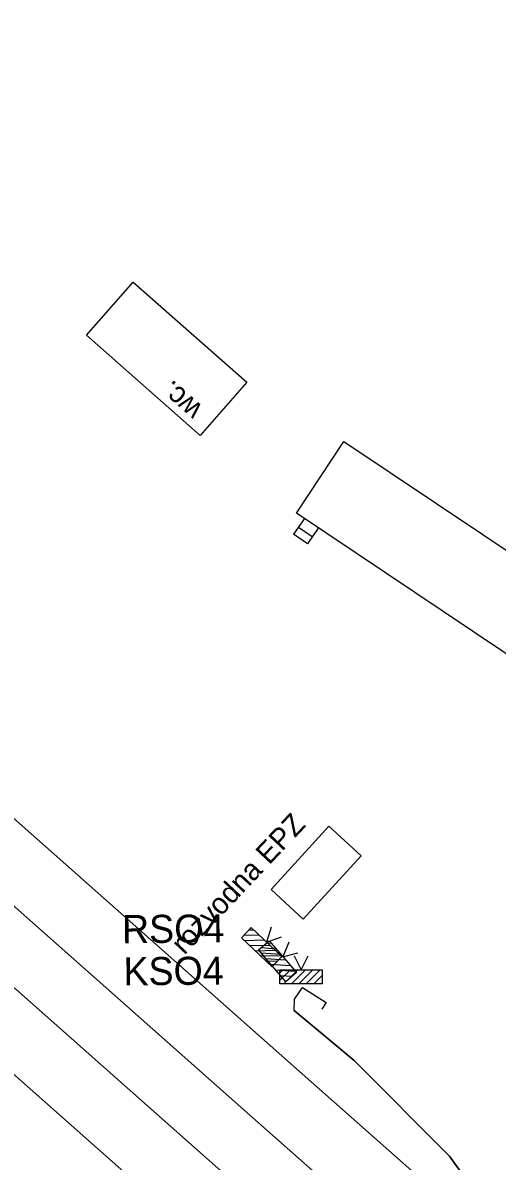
# Model space of a CAD drawing. Extents: x -496570 to -495506, y -1089156 to -1088046.
# Drawn here: x -496355.2 to -496321.4, y -1088285 to -1088203.9 of the extents above; entities that cross this region are included whole.
import ezdxf

# ---------------------------------------------------------------- set-up
doc = ezdxf.new("R2010")
doc.units = 0
for name, color, linetype in [('14', 7, 'Continuous'), ('39', 7, 'Continuous'), ('54', 7, 'Continuous'), ('PŘÍSTUPOVÉ_CESTY', 7, 'Continuous'), ('PŮVODNÍ_NÁVRH', 7, 'Continuous')]:
    doc.layers.add(name, color=color, linetype=linetype)

msp = doc.modelspace()

# ---------------------------------------------------------------- linework, layer by layer
at = {"layer": '14'}
for points in [[(-496500.326, -1088150.883), (-496478.319, -1088170.391), (-496459.205, -1088187.309), (-496440.603, -1088203.768), (-496419.398, -1088222.532), (-496401.337, -1088238.524), (-496381.863, -1088255.763), (-496363.496, -1088272.022), (-496344.908, -1088288.479), (-496325.602, -1088305.577), (-496305.115, -1088323.698), (-496285.279, -1088341.274), (-496267.778, -1088356.78), (-496248.642, -1088373.733), (-496220.391, -1088398.759), (-496201.351, -1088415.62), (-496182.974, -1088431.889), (-496164.259, -1088448.462), (-496145.687, -1088464.902), (-496132.984, -1088476.226), (-496115.09, -1088492.058), (-496092.682, -1088511.89), (-496073.961, -1088528.378)], [(-496036.118, -1088555.5), (-496048.975, -1088544.1), (-496066.196, -1088528.906), (-496086.152, -1088511.349), (-496104.929, -1088494.746), (-496123.588, -1088478.229), (-496142.293, -1088461.701), (-496160.965, -1088445.175), (-496179.891, -1088428.396), (-496198.214, -1088412.189), (-496217.292, -1088395.311), (-496245.811, -1088370.064), (-496264.918, -1088353.145), (-496281.988, -1088338.018), (-496302.247, -1088320.079), (-496322.57, -1088302.076), (-496341.966, -1088284.907), (-496360.552, -1088268.447), (-496378.713, -1088252.378), (-496398.4, -1088234.928), (-496416.447, -1088218.945), (-496437.668, -1088200.162), (-496456.103, -1088183.845), (-496474.042, -1088168.071)], [(-496082.486, -1088502.043), (-496098.63, -1088487.696), (-496117.358, -1088471.138), (-496136.056, -1088454.602), (-496154.785, -1088438.063), (-496173.551, -1088421.521), (-496192.303, -1088405.013), (-496211.05, -1088388.494), (-496229.814, -1088371.969), (-496241.71, -1088361.483), (-496259.312, -1088345.98), (-496335.952, -1088278.18), (-496354.664, -1088261.608), (-496372.853, -1088245.502), (-496392.083, -1088228.459), (-496410.817, -1088211.882), (-496431.795, -1088193.31), (-496448.334, -1088178.663)], [(-496419.776, -1088210.17), (-496413.73, -1088215.561), (-496395.384, -1088231.799), (-496375.938, -1088249.024), (-496357.661, -1088265.193), (-496339.088, -1088281.642), (-496320.817, -1088297.785), (-496278.447, -1088335.251), (-496262.212, -1088349.594), (-496242.734, -1088366.795), (-496214.147, -1088392.048), (-496195.339, -1088408.643), (-496176.8, -1088425.002), (-496157.997, -1088441.59), (-496139.148, -1088458.239), (-496120.509, -1088474.69), (-496101.775, -1088491.246), (-496088.913, -1088502.664), (-496081.326, -1088509.353), (-496072.768, -1088516.905)]]:
    msp.add_lwpolyline(points, dxfattribs=at)
at = {"layer": '39'}
for p, q in [((-496335.174, -1088239.171), (-496335.946, -1088240.283)), ((-496334.187, -1088239.856), (-496334.947, -1088240.977)), ((-496334.947, -1088240.977), (-496335.946, -1088240.283))]:
    msp.add_line(p, q, dxfattribs=at)
for points in [[(-496339.26, -1088229.466), (-496342.604, -1088233.265), (-496350.697, -1088226.124), (-496347.379, -1088222.343), (-496339.26, -1088229.466)], [(-496306.766, -1088258.19), (-496312.619, -1088254.307), (-496335.736, -1088238.781), (-496332.365, -1088233.683), (-496309.194, -1088249.189), (-496303.385, -1088253.076), (-496306.766, -1088258.19)], [(-496335.586, -1088239.787), (-496334.621, -1088240.448)]]:
    msp.add_lwpolyline(points, dxfattribs=at)
msp.add_lwpolyline([(-496335.25, -1088267.7), (-496337.549, -1088265.61), (-496333.44, -1088261.09), (-496331.13, -1088263.19)], close=True, dxfattribs=at)
at = {"layer": '54'}
msp.add_lwpolyline([(-496323.03, -1088287.1), (-496324.84, -1088284.59), (-496331.63, -1088277.78), (-496335.9, -1088274.21), (-496335.88, -1088273.41), (-496335.31, -1088272.58), (-496333.62, -1088273.64), (-496333.94, -1088274.12)], dxfattribs=at)
at = {"layer": 'PŘÍSTUPOVÉ_CESTY'}
for p, q in [((-496339.468, -1088268.856), (-496338.411, -1088268.83)), ((-496339.439, -1088269.231), (-496338.026, -1088269.195)), ((-496339.103, -1088268.472), (-496338.795, -1088268.464)), ((-496339.055, -1088269.596), (-496337.642, -1088269.56)), ((-496338.671, -1088269.962), (-496337.257, -1088269.926)), ((-496338.257, -1088269.735), (-496337.202, -1088269.814)), ((-496337.855, -1088269.389), (-496337.547, -1088269.412)), ((-496338.286, -1088270.327), (-496336.872, -1088270.291)), ((-496338.266, -1088270.111), (-496336.855, -1088270.216)), ((-496337.92, -1088270.513), (-496336.509, -1088270.618)), ((-496337.902, -1088270.692), (-496337.054, -1088270.671)), ((-496337.574, -1088270.914), (-496336.164, -1088271.02)), ((-496337.518, -1088271.058), (-496337.419, -1088271.055)), ((-496337.228, -1088271.317), (-496335.817, -1088271.422)), ((-496336.91, -1088271.538), (-496336.692, -1088271.32)), ((-496336.91, -1088272.068), (-496336.162, -1088271.32)), ((-496336.631, -1088272.32), (-496335.631, -1088271.32)), ((-496336.101, -1088272.32), (-496335.101, -1088271.32)), ((-496335.571, -1088272.32), (-496334.571, -1088271.32)), ((-496335.04, -1088272.32), (-496334.04, -1088271.32)), ((-496336.882, -1088271.718), (-496336.036, -1088271.782)), ((-496336.536, -1088272.12), (-496336.437, -1088272.127)), ((-496334.51, -1088272.32), (-496333.91, -1088271.72)), ((-496333.98, -1088272.32), (-496333.91, -1088272.25))]:
    msp.add_line(p, q, dxfattribs=at)
for points in [[(-496338.953, -1088268.314), (-496336.778, -1088270.381), (-496337.467, -1088271.106), (-496339.642, -1088269.039)], [(-496337.69, -1088269.247), (-496335.732, -1088271.521), (-496336.49, -1088272.173), (-496338.448, -1088269.899)], [(-496336.91, -1088271.32), (-496333.91, -1088271.32), (-496333.91, -1088272.32), (-496336.91, -1088272.32)]]:
    msp.add_lwpolyline(points, close=True, dxfattribs=at)
for points in [[(-496338.953, -1088268.314), (-496336.778, -1088270.381), (-496337.467, -1088271.106), (-496339.642, -1088269.039), (-496338.953, -1088268.314)], [(-496337.539, -1088268.278), (-496337.866, -1088269.348), (-496336.814, -1088268.967)], [(-496337.69, -1088269.247), (-496335.732, -1088271.521), (-496336.49, -1088272.173), (-496338.448, -1088269.899), (-496337.69, -1088269.247)], [(-496336.279, -1088269.352), (-496336.711, -1088270.384), (-496335.627, -1088270.11)], [(-496335.91, -1088270.32), (-496335.41, -1088271.32), (-496334.91, -1088270.32)], [(-496336.91, -1088271.32), (-496333.91, -1088271.32), (-496333.91, -1088272.32), (-496336.91, -1088272.32), (-496336.91, -1088271.32)]]:
    msp.add_lwpolyline(points, dxfattribs=at)
at = {"layer": 'PŮVODNÍ_NÁVRH'}
msp.add_lwpolyline([(-496335.9, -1088274.21), (-496331.63, -1088277.78), (-496324.84, -1088284.59), (-496323.03, -1088287.1)], dxfattribs=at)

# ---------------------------------------------------------------- texts
at = {"layer": '39'}
for s, rotation, p in [('wc.', 138.57587, (-496342.354, -1088231.215)), ('rozvodna EPZ', 46.72936, (-496343.72, -1088270.31))]:
    msp.add_text(s, height=1.5, rotation=rotation, dxfattribs=at).set_placement(p)
at = {"layer": 'PŘÍSTUPOVÉ_CESTY'}
for s, p in [('RSO4', (-496348.156, -1088269.427)), ('KSO4', (-496348.05, -1088272.43))]:
    msp.add_text(s, height=2, rotation=0.49925, dxfattribs=at).set_placement(p)

doc.saveas('drawing.dxf')
